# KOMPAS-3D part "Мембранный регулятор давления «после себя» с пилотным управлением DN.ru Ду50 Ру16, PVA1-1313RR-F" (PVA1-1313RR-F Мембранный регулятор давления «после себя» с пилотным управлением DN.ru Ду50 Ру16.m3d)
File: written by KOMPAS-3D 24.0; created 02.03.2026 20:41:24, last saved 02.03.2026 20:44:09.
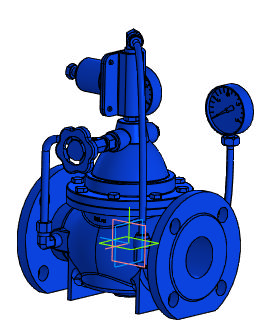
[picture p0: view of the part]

Document properties: Автор: R2D2; Полное имя файла: PVA1-1313RR-F Мембранный регулятор давления «после себя» с пилотным управлением DN.ru Ду50 Ру16.cdw

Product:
- Part/product: Мембранный регулятор давления «после себя» с пилотным управлением DN.ru Ду50 Ру16  | designation PVA1-1313RR-F
    Масса: 8.5
    Раздел спецификации: Прочие изделия
    Форматы листов документа: A2
    Примечание: D230-10617
    additional columns: D230-10617

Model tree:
1. Операция без истории:1

Expressions: PVA1-1313RR-F
Referenced files in C:\Program Files\ASCON\KOMPAS-3D v24\Libs\Pipeline\: StylesTemplate.a3d, TemplateHPH, InsulationStylesTemplate.a3d, Insulation
Referenced files in C:\Program Files\ASCON\KOMPAS-3D v24\Templates\: Констр. чертеж А3 гориз. перв. лист.cdt
Referenced files in E:\Работа\Зайцев\PVA1-1313RR-F Мембранный регулятор давления «после себя» с пилотным управлением DN.ru Ду50-200 Ру16\DN50\исходные материалы\: 
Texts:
  Отводы ГОСТ 17375-2001
  Констр. чертеж А3 гориз. перв. лист.cdt
  Точка начала. Х
  Точка начала. Y
  Точка начала. Z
